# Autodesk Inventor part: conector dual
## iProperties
Created: 2008-01
Part Number: conector dual
Document SubType Name: Modeling
Designer: eruiz-tagle
Mass: 0.15701 g
Surface Area: 3.86719 cm^2
Volume: 0.15701 cm^3
Density: 1 g/cm^3
Author: eruiz-tagle
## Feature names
1. Revolution2
2. Fillet1
3. Extrusion1
4. Fillet2
5. Extrusion2
